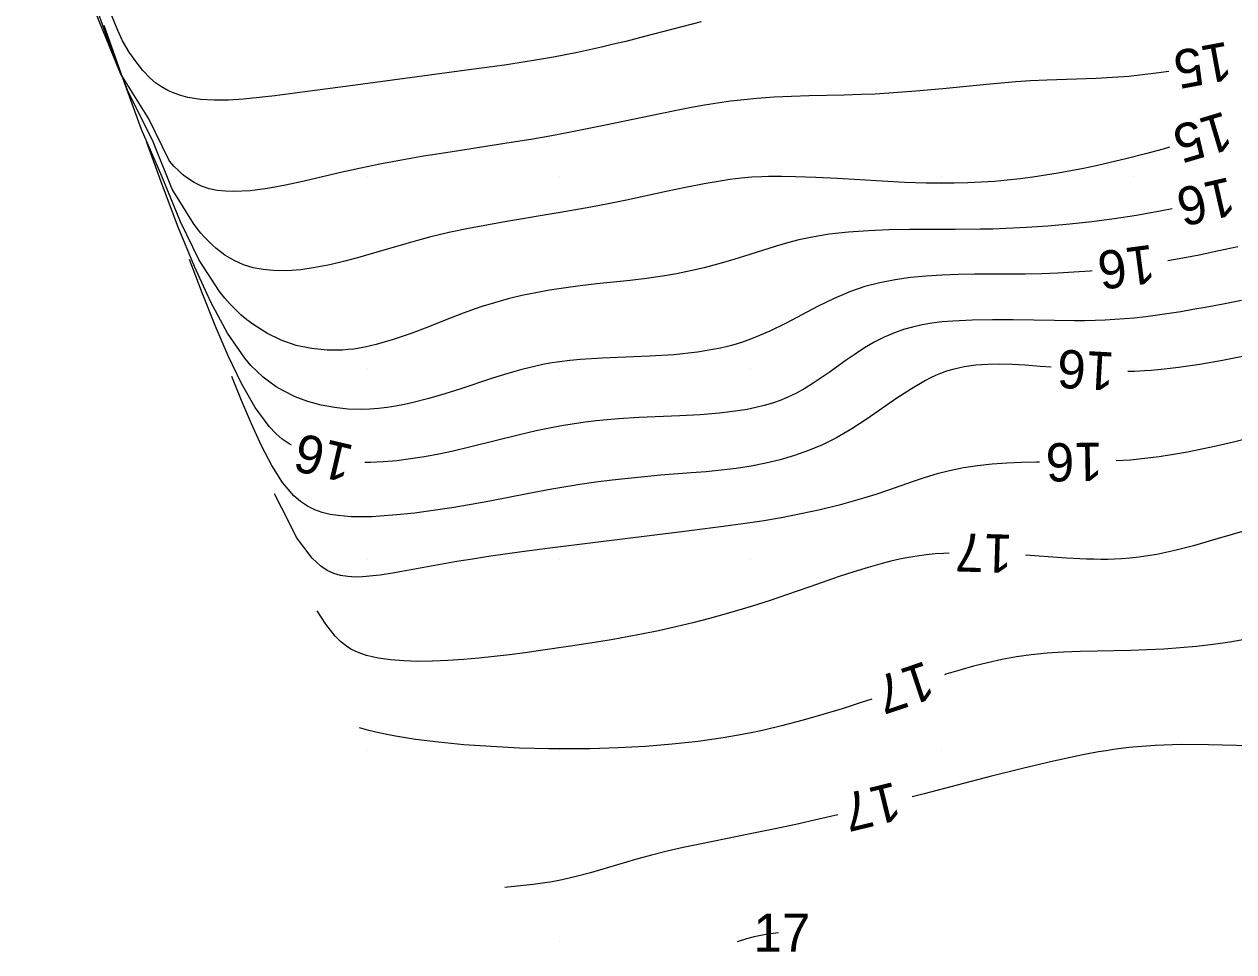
# Model space of a CAD drawing. Extents: x 2602990 to 2605851, y 618069 to 619180.
# Drawn here: x 2603152 to 2603215.3, y 618069.5 to 618118 of the extents above; entities that cross this region are included whole.
import ezdxf

# ---------------------------------------------------------------- set-up
doc = ezdxf.new("R2010")
doc.units = 0
for name, color, linetype in [('DTM Contours Major', 7, 'Continuous'), ('DTM Contours Major Text', 7, 'Continuous'), ('DTM Contours Minor', 7, 'Continuous'), ('DTM Contours Minor Text', 7, 'Continuous'), ('Exist DTM QL2 LIDAR Elevation Point', 7, 'Continuous')]:
    doc.layers.add(name, color=color, linetype=linetype)

msp = doc.modelspace()

# ---------------------------------------------------------------- linework, layer by layer
at = {"layer": 'DTM Contours Major'}
for points in [[(2603165.995, 618095.967), (2603165.873, 618096.039), (2603165.523, 618096.291), (2603165.179, 618096.59), (2603164.843, 618096.942), (2603164.101, 618097.942), (2603163.385, 618099.19), (2603162.687, 618100.638), (2603162.004, 618102.235), (2603161.331, 618103.931), (2603160.663, 618105.678)], [(2603215.67, 618103.545), (2603214.708, 618103.352), (2603213.771, 618103.174), (2603213.13, 618103.058), (2603212.502, 618102.95), (2603211.884, 618102.851), (2603211.271, 618102.762), (2603210.662, 618102.685), (2603210.052, 618102.619), (2603209.552, 618102.576), (2603209.048, 618102.54), (2603208.537, 618102.513), (2603208.017, 618102.494), (2603207.487, 618102.482), (2603206.943, 618102.477), (2603205.899, 618102.484), (2603203.734, 618102.523), (2603202.652, 618102.53), (2603201.596, 618102.515), (2603200.586, 618102.464), (2603200.026, 618102.414), (2603199.488, 618102.346), (2603198.97, 618102.258), (2603198.471, 618102.148), (2603197.992, 618102.014), (2603197.53, 618101.854), (2603196.987, 618101.62), (2603196.466, 618101.352), (2603195.964, 618101.056), (2603195.476, 618100.739), (2603194.999, 618100.41), (2603194.114, 618099.78), (2603193.698, 618099.49), (2603193.277, 618099.21), (2603192.847, 618098.945), (2603192.405, 618098.7), (2603191.947, 618098.478), (2603191.554, 618098.316), (2603191.146, 618098.172), (2603190.722, 618098.045), (2603190.281, 618097.935), (2603189.821, 618097.84), (2603189.342, 618097.76), (2603188.383, 618097.646), (2603187.367, 618097.567), (2603186.312, 618097.512), (2603184.157, 618097.417), (2603183.092, 618097.351), (2603182.506, 618097.302), (2603181.929, 618097.243), (2603181.358, 618097.174), (2603180.791, 618097.094), (2603180.227, 618097.003), (2603179.665, 618096.9), (2603178.79, 618096.718), (2603177.916, 618096.515), (2603175.31, 618095.867), (2603174.454, 618095.667), (2603173.702, 618095.507), (2603172.96, 618095.368), (2603172.231, 618095.252), (2603171.516, 618095.161), (2603170.819, 618095.098), (2603170.141, 618095.067), (2603169.841, 618095.066)]]:
    msp.add_lwpolyline(points, dxfattribs=at)
at = {"layer": 'DTM Contours Minor'}
for points in [[(2603187.429, 618118.114), (2603184.452, 618117.334), (2603183.481, 618117.087), (2603182.844, 618116.931), (2603182.212, 618116.783), (2603181.585, 618116.642), (2603180.958, 618116.508), (2603180.331, 618116.382), (2603179.7, 618116.263), (2603178.857, 618116.115), (2603178.005, 618115.977), (2603177.147, 618115.848), (2603175.418, 618115.606), (2603169.082, 618114.763), (2603166.695, 618114.442), (2603165.129, 618114.243), (2603164.305, 618114.147), (2603163.499, 618114.068), (2603162.717, 618114.019), (2603161.966, 618114.009), (2603161.254, 618114.05), (2603160.587, 618114.154), (2603160.219, 618114.249), (2603159.868, 618114.371), (2603159.532, 618114.522), (2603159.21, 618114.706), (2603158.9, 618114.923), (2603158.603, 618115.176), (2603158.232, 618115.559), (2603157.874, 618116.008), (2603157.521, 618116.524), (2603157.169, 618117.111), (2603156.929, 618117.658), (2603152.028, 618129.669)], [(2603211.914, 618111.547), (2603211.569, 618111.448), (2603210.655, 618111.199), (2603209.686, 618110.954), (2603208.743, 618110.733), (2603208.077, 618110.586), (2603207.413, 618110.447), (2603206.75, 618110.317), (2603206.087, 618110.196), (2603205.422, 618110.086), (2603204.754, 618109.987), (2603204.093, 618109.901), (2603203.426, 618109.827), (2603202.75, 618109.766), (2603202.063, 618109.718), (2603201.362, 618109.685), (2603200.646, 618109.667), (2603199.925, 618109.664), (2603199.183, 618109.676), (2603198.051, 618109.715), (2603196.885, 618109.774), (2603194.545, 618109.91), (2603193.421, 618109.969), (2603192.358, 618110.01), (2603191.629, 618110.023), (2603191.278, 618110.023), (2603190.934, 618110.017), (2603190.595, 618110.006), (2603190.075, 618109.977), (2603189.513, 618109.928), (2603188.921, 618109.856), (2603188.516, 618109.797), (2603187.579, 618109.637), (2603186.6, 618109.446), (2603185.588, 618109.233), (2603183.513, 618108.786), (2603182.471, 618108.573), (2603181.459, 618108.383), (2603179.937, 618108.12), (2603177.349, 618107.687), (2603176.3, 618107.501), (2603175.257, 618107.301), (2603174.229, 618107.084), (2603173.226, 618106.846), (2603172.594, 618106.679), (2603171.975, 618106.506), (2603170.165, 618105.974), (2603169.571, 618105.804), (2603168.789, 618105.594), (2603168.013, 618105.408), (2603167.246, 618105.257), (2603166.493, 618105.148), (2603165.758, 618105.092), (2603165.046, 618105.098), (2603164.513, 618105.151), (2603163.995, 618105.253), (2603163.491, 618105.41), (2603162.999, 618105.628), (2603162.519, 618105.913), (2603162.048, 618106.271), (2603161.851, 618106.446), (2603161.655, 618106.637), (2603161.46, 618106.842), (2603161.266, 618107.065), (2603161.072, 618107.303), (2603160.878, 618107.559), (2603159.77, 618109.364), (2603158.728, 618111.919), (2603157.456, 618114.44), (2603156.302, 618117.472), (2603155.145, 618120.705)], [(2603211.865, 618115.518), (2603211.216, 618115.421), (2603210.497, 618115.328), (2603209.773, 618115.253), (2603208.925, 618115.189), (2603208.07, 618115.145), (2603205.496, 618115.057), (2603204.642, 618115.017), (2603203.87, 618114.967), (2603203.102, 618114.906), (2603202.338, 618114.836), (2603200.06, 618114.608), (2603198.651, 618114.479), (2603197.943, 618114.423), (2603197.232, 618114.374), (2603196.515, 618114.333), (2603195.792, 618114.301), (2603194.89, 618114.274), (2603193.064, 618114.236), (2603192.149, 618114.21), (2603191.238, 618114.169), (2603190.336, 618114.105), (2603189.646, 618114.037), (2603188.96, 618113.952), (2603188.278, 618113.853), (2603187.596, 618113.742), (2603186.912, 618113.62), (2603186.224, 618113.489), (2603185.282, 618113.301), (2603182.419, 618112.702), (2603181.462, 618112.506), (2603180.511, 618112.319), (2603179.514, 618112.135), (2603178.511, 618111.962), (2603177.486, 618111.794), (2603174.074, 618111.263), (2603172.911, 618111.075), (2603171.755, 618110.875), (2603170.618, 618110.661), (2603169.632, 618110.458), (2603168.66, 618110.242), (2603166.659, 618109.776), (2603165.685, 618109.566), (2603164.743, 618109.394), (2603163.841, 618109.277), (2603162.988, 618109.233), (2603162.545, 618109.246), (2603162.117, 618109.292), (2603161.703, 618109.38), (2603161.3, 618109.516), (2603160.906, 618109.707), (2603160.519, 618109.961), (2603160.303, 618110.133), (2603160.089, 618110.329), (2603159.875, 618110.548), (2603159.647, 618110.808), (2603159.601, 618110.864), (2603158.545, 618113.028), (2603157.062, 618115.413), (2603155.756, 618118.605)], [(2603212.047, 618108.323), (2603211.509, 618108.217), (2603210.187, 618107.986), (2603209.009, 618107.807), (2603207.841, 618107.654), (2603206.687, 618107.527), (2603205.551, 618107.425), (2603204.437, 618107.348), (2603203.351, 618107.295), (2603202.676, 618107.273), (2603202.01, 618107.259), (2603200.696, 618107.248), (2603198.314, 618107.241), (2603197.239, 618107.224), (2603196.173, 618107.184), (2603195.125, 618107.113), (2603194.108, 618107.001), (2603193.131, 618106.839), (2603192.52, 618106.703), (2603191.927, 618106.547), (2603191.346, 618106.376), (2603189.634, 618105.831), (2603188.956, 618105.625), (2603188.268, 618105.431), (2603187.57, 618105.25), (2603186.86, 618105.085), (2603186.138, 618104.937), (2603185.402, 618104.808), (2603184.561, 618104.687), (2603183.705, 618104.585), (2603181.967, 618104.401), (2603181.093, 618104.302), (2603180.222, 618104.189), (2603179.495, 618104.076), (2603178.772, 618103.945), (2603178.053, 618103.793), (2603177.336, 618103.619), (2603176.621, 618103.422), (2603175.907, 618103.199), (2603174.974, 618102.869), (2603174.044, 618102.513), (2603173.122, 618102.151), (2603172.21, 618101.803), (2603171.312, 618101.49), (2603170.431, 618101.232), (2603170.135, 618101.16), (2603169.84, 618101.097), (2603169.547, 618101.044), (2603169.255, 618101), (2603168.964, 618100.967), (2603168.673, 618100.944), (2603167.859, 618100.938), (2603167.049, 618101.02), (2603166.25, 618101.193), (2603165.467, 618101.461), (2603164.706, 618101.826), (2603163.974, 618102.292), (2603163.673, 618102.521), (2603163.378, 618102.771), (2603163.088, 618103.043), (2603162.802, 618103.34), (2603162.519, 618103.663), (2603162.24, 618104.014), (2603161.182, 618105.642), (2603160.199, 618107.648), (2603159.219, 618110.046), (2603158.159, 618112.481), (2603157.182, 618115.162), (2603156.212, 618117.918)], [(2603207.859, 618105.083), (2603207.754, 618105.073), (2603206.913, 618105.011), (2603206.075, 618104.965), (2603205.24, 618104.935), (2603204.354, 618104.918), (2603201.724, 618104.906), (2603200.86, 618104.892), (2603200.005, 618104.862), (2603199.178, 618104.811), (2603198.361, 618104.732), (2603197.556, 618104.619), (2603196.763, 618104.464), (2603195.984, 618104.262), (2603195.22, 618104.007), (2603194.373, 618103.649), (2603193.537, 618103.239), (2603191.867, 618102.359), (2603191.015, 618101.939), (2603190.14, 618101.564), (2603189.864, 618101.461), (2603189.584, 618101.365), (2603189.301, 618101.275), (2603189.014, 618101.192), (2603188.722, 618101.116), (2603188.425, 618101.047), (2603187.23, 618100.837), (2603185.987, 618100.703), (2603184.723, 618100.621), (2603182.253, 618100.517), (2603181.105, 618100.447), (2603180.552, 618100.396), (2603180.021, 618100.332), (2603179.507, 618100.254), (2603179.135, 618100.185), (2603178.769, 618100.109), (2603178.406, 618100.024), (2603178.045, 618099.931), (2603177.683, 618099.831), (2603177.32, 618099.725), (2603176.511, 618099.472), (2603174.857, 618098.926), (2603174.023, 618098.658), (2603173.191, 618098.411), (2603172.368, 618098.197), (2603171.909, 618098.095), (2603171.455, 618098.009), (2603171.004, 618097.94), (2603170.555, 618097.889), (2603170.107, 618097.855), (2603169.661, 618097.841), (2603168.95, 618097.862), (2603168.244, 618097.936), (2603167.547, 618098.067), (2603166.864, 618098.257), (2603166.199, 618098.509), (2603165.557, 618098.824), (2603165.207, 618099.031), (2603164.864, 618099.263), (2603164.529, 618099.523), (2603164.2, 618099.817), (2603163.876, 618100.147), (2603163.557, 618100.517), (2603162.654, 618101.828), (2603161.778, 618103.45), (2603160.924, 618105.32), (2603160.086, 618107.376), (2603159.259, 618109.556), (2603158.437, 618111.798)], [(2603215.472, 618106.346), (2603214.477, 618106.127), (2603213.454, 618105.913), (2603212.41, 618105.711), (2603211.823, 618105.607)], [(2603215.901, 618100.64), (2603214.669, 618100.397), (2603213.487, 618100.192), (2603212.374, 618100.029), (2603211.643, 618099.941), (2603211.29, 618099.906), (2603210.943, 618099.877), (2603210.6, 618099.854), (2603210.078, 618099.83), (2603209.719, 618099.823)], [(2603205.726, 618100.044), (2603205.146, 618100.093), (2603204.356, 618100.152), (2603203.694, 618100.189), (2603203.044, 618100.206), (2603202.406, 618100.197), (2603201.783, 618100.154), (2603201.174, 618100.069), (2603200.58, 618099.936), (2603200.255, 618099.837), (2603199.933, 618099.721), (2603199.671, 618099.612), (2603199.41, 618099.49), (2603199.148, 618099.356), (2603198.41, 618098.926), (2603197.659, 618098.43), (2603196.104, 618097.354), (2603195.297, 618096.827), (2603194.466, 618096.345), (2603193.761, 618095.995), (2603193.04, 618095.692), (2603192.305, 618095.431), (2603191.558, 618095.211), (2603190.8, 618095.027), (2603190.033, 618094.877), (2603189.256, 618094.757), (2603188.473, 618094.662), (2603187.685, 618094.585), (2603186.894, 618094.52), (2603185.303, 618094.397), (2603184.456, 618094.322), (2603183.609, 618094.237), (2603182.763, 618094.141), (2603181.92, 618094.034), (2603181.08, 618093.913), (2603180.245, 618093.779), (2603179.605, 618093.667), (2603178.326, 618093.425), (2603176.38, 618093.049), (2603175.389, 618092.869), (2603174.391, 618092.702), (2603173.402, 618092.552), (2603172.435, 618092.424), (2603171.504, 618092.323), (2603170.625, 618092.254), (2603170.228, 618092.233), (2603169.846, 618092.222), (2603169.476, 618092.221), (2603169.12, 618092.231), (2603168.775, 618092.253), (2603168.441, 618092.288), (2603168.017, 618092.356), (2603167.611, 618092.456), (2603167.219, 618092.596), (2603166.843, 618092.782), (2603166.479, 618093.024), (2603166.128, 618093.328), (2603165.534, 618094.03), (2603164.97, 618094.915), (2603164.429, 618095.947), (2603163.906, 618097.09), (2603163.394, 618098.305), (2603162.888, 618099.557)], [(2603216.153, 618096.356), (2603215.251, 618096.133), (2603214.343, 618095.923), (2603213.597, 618095.762), (2603212.852, 618095.614), (2603212.107, 618095.482), (2603211.362, 618095.367), (2603210.617, 618095.271), (2603209.87, 618095.198), (2603209.117, 618095.148)], [(2603205.118, 618095.08), (2603204.951, 618095.078), (2603204.167, 618095.062), (2603203.393, 618095.03), (2603202.63, 618094.978), (2603201.876, 618094.899), (2603201.135, 618094.787), (2603200.406, 618094.638), (2603199.768, 618094.472), (2603199.136, 618094.279), (2603198.503, 618094.067), (2603197.216, 618093.617), (2603196.551, 618093.395), (2603195.611, 618093.108), (2603194.639, 618092.843), (2603193.644, 618092.601), (2603192.634, 618092.381), (2603191.616, 618092.183), (2603190.6, 618092.008), (2603189.591, 618091.854), (2603188.578, 618091.715), (2603186.414, 618091.441), (2603181.765, 618090.874), (2603179.503, 618090.585), (2603178.052, 618090.391), (2603176.309, 618090.146), (2603175.469, 618090.02), (2603174.655, 618089.891), (2603173.873, 618089.759), (2603171.764, 618089.371), (2603171.285, 618089.287), (2603170.634, 618089.184), (2603170.26, 618089.136), (2603169.899, 618089.1), (2603169.722, 618089.088), (2603169.325, 618089.079), (2603168.941, 618089.1), (2603168.569, 618089.16), (2603168.21, 618089.266), (2603167.863, 618089.427), (2603167.53, 618089.651), (2603167.087, 618090.073), (2603166.256, 618091.138), (2603165.873, 618091.932), (2603165.491, 618092.673), (2603165.114, 618093.437)], [(2603216.205, 618091.608), (2603214.16, 618090.999), (2603213.159, 618090.716), (2603212.185, 618090.467), (2603211.25, 618090.263), (2603210.78, 618090.18), (2603210.319, 618090.113), (2603209.839, 618090.06), (2603209.392, 618090.027), (2603209.038, 618090.011), (2603208.681, 618090.003), (2603208.317, 618090.002), (2603207.946, 618090.008), (2603207.565, 618090.019), (2603206.513, 618090.071), (2603204.384, 618090.216)], [(2603200.388, 618090.332), (2603200.082, 618090.317), (2603199.649, 618090.284), (2603199.176, 618090.234), (2603198.711, 618090.171), (2603198.252, 618090.095), (2603197.797, 618090.006), (2603197.342, 618089.904), (2603196.885, 618089.789), (2603196.145, 618089.582), (2603195.395, 618089.35), (2603194.636, 618089.099), (2603193.106, 618088.568), (2603191.883, 618088.145), (2603190.969, 618087.84), (2603190.039, 618087.545), (2603189.565, 618087.4), (2603188.725, 618087.155), (2603187.864, 618086.918), (2603186.986, 618086.69), (2603186.096, 618086.475), (2603185.198, 618086.272), (2603184.296, 618086.086), (2603183.556, 618085.945), (2603182.815, 618085.814), (2603182.074, 618085.692), (2603180.587, 618085.463), (2603179.028, 618085.236), (2603178.214, 618085.122), (2603177.402, 618085.015), (2603176.593, 618084.917), (2603175.789, 618084.832), (2603174.994, 618084.762), (2603174.175, 618084.708), (2603173.376, 618084.676), (2603172.605, 618084.671), (2603171.872, 618084.693), (2603171.186, 618084.747), (2603170.555, 618084.835), (2603170.228, 618084.901), (2603169.921, 618084.979), (2603169.632, 618085.073), (2603169.361, 618085.184), (2603169.108, 618085.313), (2603168.871, 618085.463), (2603168.569, 618085.707), (2603168.292, 618085.986), (2603168.035, 618086.294), (2603167.795, 618086.623), (2603167.564, 618086.966), (2603167.339, 618087.317)], [(2603215.951, 618085.839), (2603215.052, 618085.676), (2603214.185, 618085.547), (2603213.322, 618085.447), (2603212.461, 618085.37), (2603211.603, 618085.314), (2603210.746, 618085.274), (2603209.893, 618085.247), (2603208.117, 618085.21), (2603207.239, 618085.188), (2603206.37, 618085.152), (2603205.512, 618085.096), (2603204.669, 618085.011), (2603203.9, 618084.901), (2603203.143, 618084.763), (2603202.398, 618084.6), (2603201.663, 618084.416), (2603200.937, 618084.215), (2603200.218, 618083.998), (2603200.139, 618083.973)], [(2603196.347, 618082.701), (2603195.779, 618082.511), (2603194.795, 618082.194), (2603193.784, 618081.885), (2603192.751, 618081.59), (2603191.698, 618081.314), (2603190.63, 618081.063), (2603189.955, 618080.921), (2603189.271, 618080.791), (2603188.572, 618080.672), (2603187.267, 618080.487), (2603185.909, 618080.337), (2603184.508, 618080.222), (2603183.074, 618080.143), (2603181.618, 618080.099), (2603180.032, 618080.089), (2603179.445, 618080.096), (2603177.928, 618080.137), (2603176.442, 618080.211), (2603175.018, 618080.313), (2603173.689, 618080.439), (2603172.485, 618080.587), (2603171.438, 618080.752), (2603170.986, 618080.839), (2603170.574, 618080.93), (2603170.053, 618081.061), (2603169.565, 618081.197)], [(2603220, 618080), (2603218.453, 618080.102), (2603216.919, 618080.194), (2603215.41, 618080.267), (2603213.94, 618080.311), (2603212.52, 618080.316), (2603211.164, 618080.272), (2603210.463, 618080.225), (2603209.776, 618080.159), (2603209.381, 618080.113), (2603208.987, 618080.06), (2603208.59, 618080), (2603208.189, 618079.934), (2603207.368, 618079.784), (2603205.836, 618079.459), (2603204.213, 618079.075), (2603202.528, 618078.65), (2603199.078, 618077.75), (2603198.459, 618077.591)], [(2603194.574, 618076.64), (2603193.579, 618076.412), (2603192.378, 618076.148), (2603191.209, 618075.899), (2603190.074, 618075.666), (2603187.348, 618075.117), (2603186.486, 618074.934), (2603185.645, 618074.743), (2603184.825, 618074.539), (2603183.996, 618074.312), (2603181.632, 618073.621), (2603180.883, 618073.419), (2603180.153, 618073.249), (2603179.638, 618073.15), (2603179.131, 618073.069), (2603178.631, 618073.001), (2603178.135, 618072.945), (2603177.151, 618072.849)], [(2603191.456, 618070.485), (2603190.913, 618070.406), (2603190.534, 618070.337), (2603190.184, 618070.26), (2603189.796, 618070.156), (2603189.302, 618070)]]:
    msp.add_lwpolyline(points, dxfattribs=at)
at = {"layer": 'Exist DTM QL2 LIDAR Elevation Point'}
for p, q in [((2603160, 618110), (2603160, 618110)), ((2603170, 618110), (2603170, 618110)), ((2603180, 618110), (2603180, 618110)), ((2603190, 618110), (2603190, 618110)), ((2603200, 618110), (2603200, 618110)), ((2603210, 618110), (2603210, 618110)), ((2603170, 618100), (2603170, 618100)), ((2603180, 618100), (2603180, 618100)), ((2603190, 618100), (2603190, 618100)), ((2603200, 618100), (2603200, 618100)), ((2603210, 618100), (2603210, 618100)), ((2603170, 618090), (2603170, 618090)), ((2603180, 618090), (2603180, 618090)), ((2603190, 618090), (2603190, 618090)), ((2603200, 618090), (2603200, 618090)), ((2603210, 618090), (2603210, 618090)), ((2603170, 618080), (2603170, 618080)), ((2603180, 618080), (2603180, 618080)), ((2603190, 618080), (2603190, 618080)), ((2603200, 618080), (2603200, 618080)), ((2603210, 618080), (2603210, 618080)), ((2603180, 618070), (2603180, 618070)), ((2603190, 618070), (2603190, 618070))]:
    msp.add_line(p, q, dxfattribs=at)

# ---------------------------------------------------------------- texts
at = {"layer": 'DTM Contours Major Text'}
msp.add_text('16', height=2, rotation=166.8221, dxfattribs=at).set_placement((2603169.347, 618095.936))
at = {"layer": 'DTM Contours Minor Text'}
for s, rotation, p in [('15', 190.43193, (2603214.932, 618117.083)), ('15', 196.63969, (2603214.79, 618113.442)), ('16', 192.91311, (2603215.047, 618110.002)), ('16', 187.54225, (2603211.003, 618106.463)), ('16', 176.83389, (2603209.073, 618100.812)), ('16', 180.98123, (2603208.4, 618096.116)), ('17', 178.32407, (2603203.715, 618091.287)), ('17', 198.54499, (2603199.154, 618084.707)), ('17', 193.76489, (2603197.544, 618078.383))]:
    msp.add_text(s, height=2, rotation=rotation, dxfattribs=at).set_placement(p)
msp.add_text('17', height=2, dxfattribs=at).set_placement((2603190.157, 618069.485))

doc.saveas('drawing.dxf')
